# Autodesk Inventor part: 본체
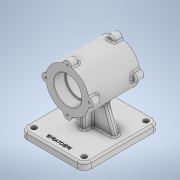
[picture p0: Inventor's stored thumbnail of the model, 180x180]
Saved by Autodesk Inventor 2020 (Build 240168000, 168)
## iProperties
Created: 2022-11
Part Number: 본체
Material: 일반
Document SubType Name: Modeling
Designer: owner
Density: 1 g/cm^3
Appearance: 기본값
Mass: 450.145 g
Surface Area: 796.917 cm^2
Volume: 450.145 cm^3
Author: owner
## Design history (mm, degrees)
sketch "스케치1"
  geometry: C1 r 37 at (0, 0); 1 further point
  constraints: 1 centre point, 1 coincident
  dimensions: "d0" = 74 diameter of C1
extrude "돌출1" new body sketch "스케치1" distance "d1" = 87; taper "d2" = 0 deg
sketch "스케치2"
  geometry: C1 r 23.5 at (0, 0); 1 further point
  constraints: 1 centre point, 1 coincident
  dimensions: "d3" = 47 diameter of C1
extrude "돌출2" cut sketch "스케치2" distance "d4" = 19; taper "d5" = 0 deg
fillet "모깎기1" dims "d6" = 1
sketch "스케치3"
  geometry: C1 r 21 at (0, 0); 1 further point
  constraints: 1 centre point, 1 coincident
  dimensions: "d7" = 42 diameter of C1
extrude "돌출3" cut sketch "스케치3" distance "d8" = 24.5; taper "d9" = 0 deg
node "작업 평면1"
sketch "스케치4"
  geometry: A1 r 37 centre (0, 0) between (0, 37) and (-6.969, 36.338) reference; A2 r 7 centre (0, 37) between (6.969, 36.338) and (-6.969, 36.338); 1 further point
  constraints: 5 point on circle, 1 centre point, 1 vertical alignment
  dimensions: "d11" = 14 diameter of A2
extrude "돌출4" join sketch "스케치4" distance "d12" = 14; taper "d13" = 0 deg
sketch "스케치5"
  geometry: A1 r 7 centre (0, 37) between (6.969, 36.338) and (-6.969, 36.338) reference; 2 further points
  constraints: 1 coincident
hole "구멍1" sketch "스케치5" at (0, 37) diameter "d14" = 3.242; stored, may be unused: countersink angle "d18" = 82 deg, drill point angle "d20" = 118 deg; dims "d15" = 8, "d16" = 3.023, "d17" = 2, "d19" = 10
node "작업 평면2"
sketch "스케치6"
  geometry: L1 (55, 26.5)-(-55, 26.5); L2 (-55, 26.5)-(-55, -103.5); L3 (-55, -103.5)-(55, -103.5); L4 (55, -103.5)-(55, 26.5); L5 (55, 26.5)-(-55, -103.5); L6 (-55, 26.5)-(55, -103.5); L7 (-6.969, 0)-(-36.338, 0) reference; 3 further points
  constraints: 12 end point, 3 midpoint, 2 parallel, 1 horizontal, 1 perpendicular, 1 vertical alignment
  dimensions: "d25" = 110 distance of L3.end L2.end; "d26" = 130 distance of L2.end L1.end; "d27" = 26.5 distance between parallel lines of L7 L1
extrude "돌출5" join sketch "스케치6" distance "d28" = 12; taper "d29" = 0 deg
node "작업 평면3"
fillet "모깎기2" dims "d40" = 3
fillet "모깎기3" dims "d41" = 3
fillet "모깎기4" dims "d42" = 3
fillet "모깎기5" dims "d43" = 3
fillet "모깎기6" dims "d44" = 3
fillet "모깎기7" dims "d45" = 3
fillet "모깎기8" dims "d46" = 3
fillet "모깎기9" dims "d47" = 3
fillet "모깎기10" dims "d48" = 3
fillet "모깎기11" dims "d49" = 3
fillet "모깎기12" dims "d50" = 3
fillet "모깎기13" dims "d51" = 3
fillet "모깎기14" dims "d52" = 3
fillet "모깎기15" dims "d53" = 3
fillet "모깎기16" dims "d54" = 3
fillet "모깎기17" dims "d55" = 3
fillet "모깎기18" dims "d57" = 12
sketch "스케치11"
  geometry: A1 r 12 centre (-43, 91.5) between (-43, 103.5) and (-55, 91.5) reference; A2 r 12 centre (43, 91.5) between (55, 91.5) and (43, 103.5) reference; A3 r 12 centre (43, -14.5) between (43, -26.5) and (55, -14.5) reference; A4 r 12 centre (-43, -14.5) between (-55, -14.5) and (-43, -26.5) reference; 5 further points
  constraints: 4 coincident
hole "구멍2" sketch "스케치11" at (-43, 91.5), (43, 91.5), (43, -14.5), (-43, -14.5) diameter "d58" = 9; stored, may be unused: countersink angle "d62" = 82 deg, drill point angle "d64" = 118 deg; dims "d59" = 8, "d60" = 3.023, "d61" = 2, "d63" = 10
node "작업 평면5"
sketch "스케치14"
  geometry: L1 (-25.336, -26.964)-(-41, -70); L2 (25.336, -26.964)-(41, -70); L3 (55, -70)-(55, -82) reference; L4 (43, -70)-(-43, -70) reference; L5 (-55, -82)-(-55, -70) reference; L6 (-47.5, -70)-(-38.5, -70) reference; L7 (43, -70)-(55, -70) reference; L8 (-41, -70)-(41, -70); L9 (38.5, -70)-(47.5, -70) reference; C1 r 37 at (0, 0); A1 r 37 centre (0, 0) between (-35.863, -9.104) and (-9.104, -35.863) reference; A2 r 37 centre (0, 0) between (9.104, -35.863) and (35.863, -9.104) reference; 3 further points
  constraints: 6 end point, 4 point on line, 2 point on circle, 1 centre point, 1 coincident
  dimensions: "d72" = 14 distance from line of L3 L2.end; "d73" = 14 distance from line of L5 L1.end; "d74" = 110 deg angle of L6 L1; "d75" = 110 deg angle of L7 L2; "d76" = 74 diameter of C1
extrude "돌출7" join sketch "스케치14" stored distance "d77" = 10; taper "d78" = 0 deg
sketch "스케치15"
  geometry: L1 (-70, -91.5)-(-70, 14.5) reference; L2 (-70, -23.5)-(-37, -23.5); L3 (-26.964, -38.5)-(-70, -38.5) reference; 1 further point
  constraints: 2 end point, 1 horizontal, 1 point on line
  dimensions: "d79" = 15 distance between parallel lines of L3 L2
feature "리브1" sketch "스케치15" dims "d80" = 1, "d81" = 10, "d82" = 0, "d83" = 0, "d84" = 1, "d85" = 1
node "작업 평면6"
sketch "스케치16"
  geometry: L1 (77, 43.5)-(-77, 43.5) reference; 2 further points
  constraints: 1 vertical alignment, 1 other
  dimensions: "d87" = 58 distance from line of L1 point (0, -14.5)
feature "엠보싱1" sketch "스케치16" dims "d10" = -43.5, "d88" = 0.5, "d89" = 0
fillet "모깎기19" dims "d90" = 3
fillet "모깎기20" dims "d91" = 3
chamfer "모따기2" distance "d95" = 1; stored, may be unused: second distance "d96" = 2, angle "d97" = 45 deg
node "솔리드1"
mirror "미러1"
pattern_circular "원형 패턴1" dims angle "d22" = 360 deg
mirror "미러2"
mirror "미러3"
node "작업 평면7"
feature "A9D066F2-1C7D-4E18-AEED-F7BC21143FA4" dims "d58" = 9, "d59" = 8, "d60" = 3.023, "d61" = 2, "d62" = 82 deg, "d63" = 10, "d64" = 118 deg
other parameters: "d24" = -82, "d30" = -43.5, "d71" = -43.5, "d86" = -43.5
